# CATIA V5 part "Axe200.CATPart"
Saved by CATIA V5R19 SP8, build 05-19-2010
Part number: Axe200
Bounding box of the stored display mesh (mm): x 0 to 350, y -15 to 15, z -15 to 15
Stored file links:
  J:\Travail\2e année\IAO\Projet\Axe200.CATPart
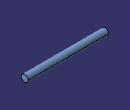
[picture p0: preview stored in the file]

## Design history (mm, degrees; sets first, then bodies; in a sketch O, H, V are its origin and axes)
Body1 (main body)
  Sketch1 on yz-plane, origin (0, 0, 0), H (0, 1, 0), V (0, 0, 1)
    circle A1 centre (0, 0) radius 15
    radius A1 = 15
  Pad1: profile Sketch1, direction (1, 0, 0), length 350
